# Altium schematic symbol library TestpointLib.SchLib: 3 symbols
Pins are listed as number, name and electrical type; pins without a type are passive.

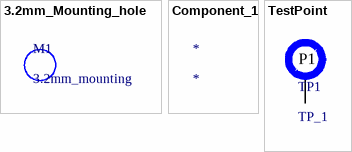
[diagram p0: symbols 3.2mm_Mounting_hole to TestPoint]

## 3.2mm_Mounting_hole
designator M1, comment 3.2mm_mounting

## Component_1
designator *

## TestPoint
designator TP1, comment TP_1  (no BOM)
footprint PCBComponent_1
